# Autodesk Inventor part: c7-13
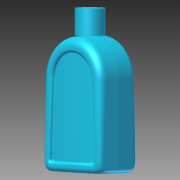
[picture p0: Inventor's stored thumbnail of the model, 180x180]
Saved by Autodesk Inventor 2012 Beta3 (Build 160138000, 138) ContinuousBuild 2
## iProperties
Created: 2010-12
Part Number: c7-13
Material: Default
Document SubType Name: Modeling
Designer: Beta-8540w
Density: 1 g/cm^3
Author: Beta-8540w
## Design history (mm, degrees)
sketch "Sketch1"
  geometry: L1 (-25, 0)-(25, 0); L2 (25, 0)-(25, 80); L3 (25, 80)-(-25, 80); L4 (-25, 80)-(-25, 0); 2 further points
  constraints: 8 end point, 2 parallel, 1 coincident, 1 horizontal, 1 midpoint, 1 perpendicular
  dimensions: "d0" = 50 distance of L3.end L2.end; "d1" = 80 distance of L2.end L1.end
extrude "Extrusion1" new body sketch "Sketch1" distance "d2" = 15; taper "d3" = 0 deg
feature "FaceDraft1" dims angle "d4" = -2 deg
fillet "Fillet1"
fillet "Fillet2" dims "d5" = 8, "d6" = 8, "d7" = 8, "d8" = 8, "d9" = 8, "d10" = 8, "d11" = 3, "d12" = 3, "d13" = 3, "d14" = 6, "d15" = 5
sketch "Sketch2"
  geometry: L1 (5.522, 12)-(38.474, 12) reference; L2 (0, 0)-(43.996, 0) reference; L3 (41.757, 6.83)-(41.995, 0); L4 (41.925, 2)-(2.071, 2); L5 (2.001, 0)-(2.24, 6.83); L6 (5.522, 10)-(38.474, 10); A1 r 5.284 centre (38.474, 6.716) between (43.755, 6.9) and (38.474, 12) reference; A2 r 5.284 centre (5.522, 6.716) between (5.522, 12) and (0.241, 6.9) reference; A3 r 3.284 centre (38.474, 6.716) between (41.757, 6.83) and (38.474, 10); A4 r 3.284 centre (5.522, 6.716) between (5.522, 10) and (2.24, 6.83); 1 further point
  constraints: 8 end point, 4 point on circle, 4 point on line, 2 centre point, 1 other
  dimensions: "d16" = 2 radial gap between concentric circles of A2 A4
extrude "Extrusion2" cut sketch "Sketch2" distance "d17" = 1; taper "d18" = 0 deg
feature "FaceDraft2" dims angle "d19" = 15 deg
sketch "Sketch3" dims "d20" = 2.5
  geometry: L1 (16.476, 3)-(-16.476, 3) reference; L2 (16.476, 5.5)-(-16.476, 5.5); 9 further points
  constraints: 2 end point, 2 parallel, 1 horizontal alignment, 19 other
extrude "Extrusion3" cut sketch "Sketch3" distance "d21" = 3; taper "d22" = 0 deg
feature "FaceDraft3" dims angle "d23" = 10 deg
workplane "Work Plane1"
sketch "Sketch4"
  geometry: L1 (41.1, -1.222)-(41.476, -12) reference; L2 (41.476, -12)-(-8.524, -12) reference; L3 (-8.524, -12)-(-8.147, -1.222) reference; L4 (-3.776, 3)-(-1.272, 3) reference; L5 (-0.743, 0)-(33.695, 0) reference; L6 (34.225, 3)-(36.728, 3) reference; L7 (-11.024, -1.856)-(43.976, -1.856); A1 r 100 centre (16.476, -98) between (43.976, -1.856) and (-11.024, -1.856); 2 further points
  constraints: 2 end point, 2 point on circle, 1 centre point, 1 midpoint, 1 parallel, 1 vertical alignment, 4 other
  dimensions: "d25" = 100 radius of A1; "d26" = 14 distance edge to line of A1 L2; "d27" = 55 distance of L7.start L7.end
extrude_surface "ExtrusionSrf1" sketch "Sketch4" dims "d28" = 86, "d29" = 0
feature "Replace Face1"
fillet "Fillet3" dims "d34" = 1, "d35" = 2
mirror "Mirror1"
fillet "Fillet4" dims "d36" = 20
workplane "Work Plane3"
sketch "Sketch6"
  geometry: C1 r 9 at (0, 0); 1 further point
  constraints: 1 centre point, 1 coincident
  dimensions: "d38" = 18 diameter of C1
extrude "Top Boss" join sketch "Sketch6" distance "d39" = 16; taper "d40" = 0 deg
body "Solid1"
body "Srf1"
node "Project Cut Edges1"
